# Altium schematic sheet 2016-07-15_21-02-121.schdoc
size 260 x 140 mm; SheetNumber: 1; SheetTotal: 1
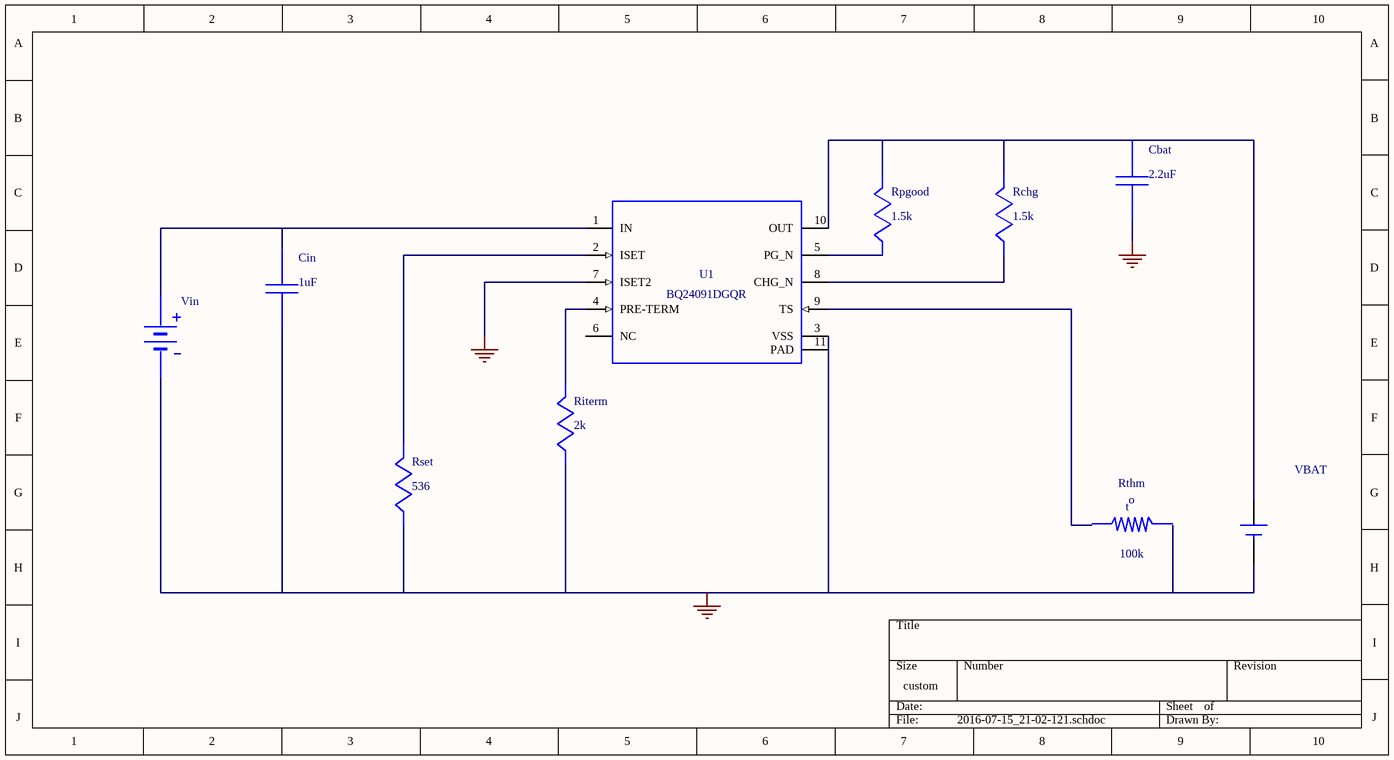
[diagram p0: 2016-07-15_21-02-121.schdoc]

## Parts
Cbat  value 2.2uF  (hidden comment: GRM188R61A225KE34D)
Cin  value 1uF  (hidden comment: GRM188R61A105KA61D)
Rchg  value 1.5k  (hidden comment: CRCW04021K50FKED)
Riterm  value 2k  (hidden comment: CRCW04022K00FKED)
Rpgood  value 1.5k  (hidden comment: CRCW04021K50FKED)
Rset  value 536  (hidden comment: CRCW0402536RFKED)
Rthm  value 100k  (hidden comment: NCP15WF104E03RC)
U1  BQ24091DGQR
VBAT  WB_BATTERY_SINGLE_USFP  (value not drawn)
Vin  WB_BATTERY  (value not drawn)

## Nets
0: Cbat.2 Cin.2 Riterm.2 Rset.2 U1.3(VSS) U1.7(ISET2) U1.11(PAD) VBAT.2(-) Vin.2(-)
NetCbat_1: Cbat.1 Rchg.1 Rpgood.1 U1.10(OUT) VBAT.1(+)
NetCin_1: Cin.1 U1.1(IN) Vin.1(+)
NetRchg_2: Rchg.2 U1.8(CHG_N)
NetRiterm_1: Riterm.1 U1.4(PRE-TERM)
NetRpgood_2: Rpgood.2 U1.5(PG_N)
NetRset_1: Rset.1 U1.2(ISET)

Not connected (* = marked no-connect by the designer): Rthm 1 2; U1 6(NC) 9(TS)

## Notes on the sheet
- (near Rthm) t
- (near Rthm) o

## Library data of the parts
Cbat = GRM188R61A225KE34D: GRM188R61A225KE3; Manufacturer Name: MuRata
Cin = GRM188R61A105KA61D: GRM188R61A105KA6; Manufacturer Name: MuRata
Rchg Rpgood = CRCW04021K50FKED: Manufacturer Name: Vishay-Dale
Riterm = CRCW04022K00FKED: Manufacturer Name: Vishay-Dale
Rset = CRCW0402536RFKED: Manufacturer Name: Vishay-Dale
Rthm = NCP15WF104E03RC: Manufacturer Name: MuRata
U1 = BQ24091DGQR: Manufacturer Name: Texas Instruments
VBAT = WB_BATTERY_SINGLE_USFP: WB_BATTERY_SINGL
